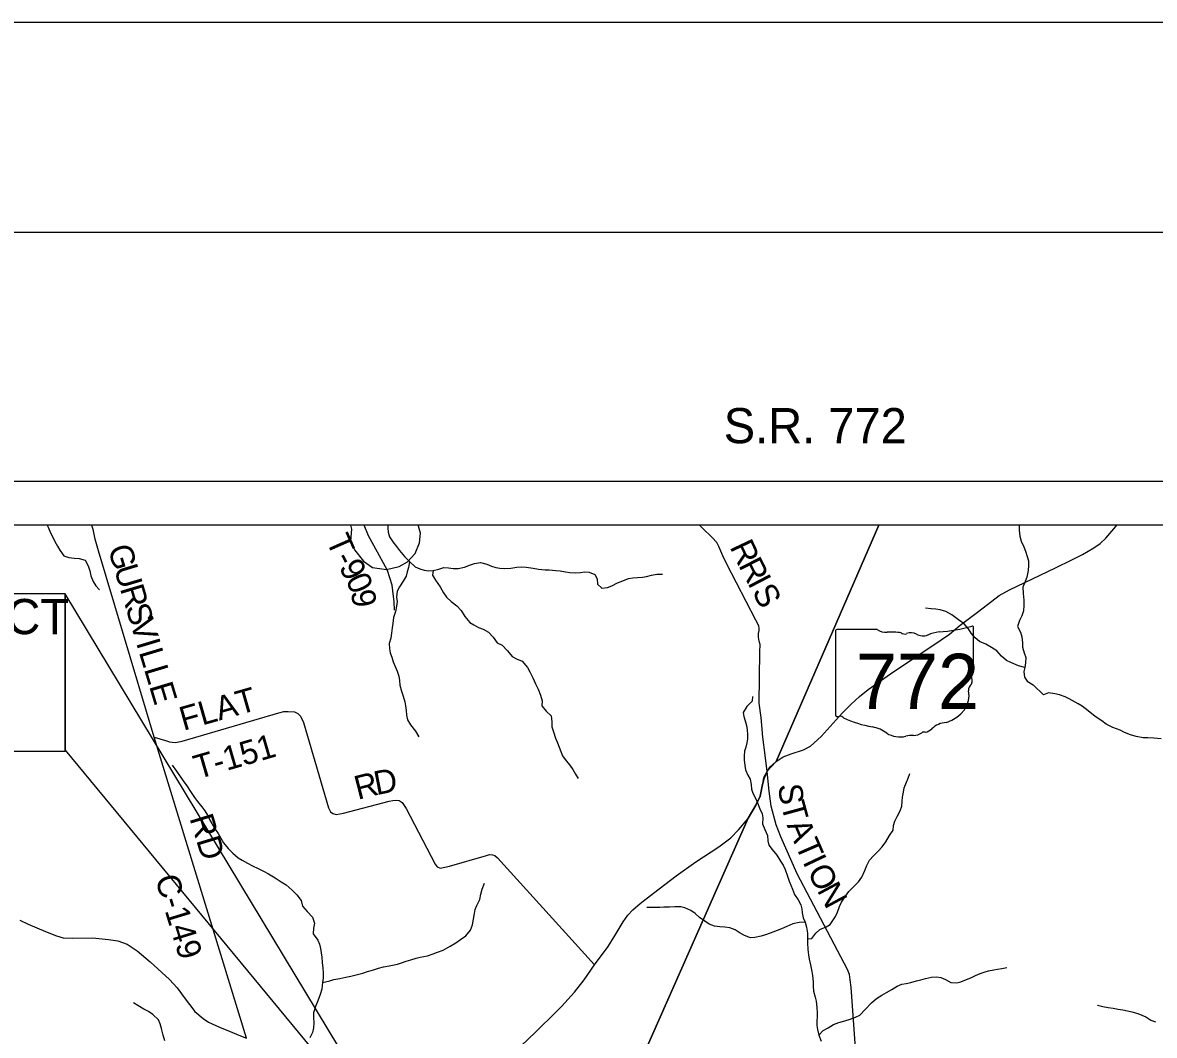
# Model space of a CAD drawing. Extents: x 0 to 34, y 0 to 22.
# Drawn here: x 3.817 to 6.52, y 19.582 to 22 of the extents above; entities that cross this region are included whole.
import ezdxf

# ---------------------------------------------------------------- set-up
doc = ezdxf.new("R2010")
doc.units = 0
for name, color, linetype in [('Default', 7, 'Continuous'), ('GM_X_County_Road', 7, 'Continuous'), ('GM_X_County_Road_Text', 7, 'Continuous'), ('GM_X_Minor_River', 7, 'Continuous'), ('GM_X_Rail_Line', 7, 'Continuous'), ('GM_X_State_Location', 7, 'Continuous'), ('GM_X_State_Route', 7, 'Continuous'), ('GM_X_State_Shield', 7, 'Continuous'), ('GM_X_Township_Road', 7, 'Continuous'), ('GM_X_Township_Road_Text', 7, 'Continuous'), ('SH_Border', 7, 'Continuous'), ('SH_Cut_Line', 7, 'Continuous'), ('SH_Text', 7, 'Continuous')]:
    doc.layers.add(name, color=color, linetype=linetype)

msp = doc.modelspace()

# ---------------------------------------------------------------- linework, layer by layer
at = {"layer": 'Default'}
for points in [[(9.087, 13.8822), (2.1062, 13.8822), (2.1062, 20.9054), (9.087, 20.9054)], [(5.8621, 20.8), (2.8183, 20.8), (3.0244, 19.9995), (3.1893, 19.3592), (4.7641, 19.2419), (4.831, 19.2363), (5.1554, 19.2083), (5.1782, 19.2598), (5.5496, 20.1004), (5.5679, 20.1313), (5.5783, 20.1528), (5.5834, 20.1771), (5.5869, 20.1933), (5.5951, 20.2127), (5.6047, 20.2229), (5.6166, 20.2359)], [(9, 18.8941), (9, 20.8), (5.8621, 20.8), (5.6166, 20.2359), (5.6047, 20.2229), (5.5951, 20.2127), (5.5869, 20.1933), (5.5834, 20.1771), (5.5783, 20.1528), (5.5679, 20.1313), (5.5496, 20.1004), (5.1782, 19.2598), (5.1554, 19.2083), (5.3224, 19.1939), (5.8337, 19.1499), (6.226, 19.1161), (6.8442, 19.0679), (8.0305, 18.9725), (8.8762, 18.9027)]]:
    msp.add_lwpolyline(points, close=True, dxfattribs=at)
at = {"layer": 'GM_X_County_Road'}
for points in [[(4.3522, 19.5749), (4.1318, 20.2937), (4.0556, 20.5466), (3.9987, 20.7384), (3.9908, 20.7664), (3.9869, 20.7867), (3.9826, 20.8)], [(3.8106, 19.8567), (3.8307, 19.8474), (3.8722, 19.8295), (3.898, 19.8193), (3.9145, 19.8144), (3.9359, 19.8139), (3.9841, 19.8144), (4.0229, 19.8108), (4.0448, 19.8072), (4.067, 19.7996), (4.0907, 19.784), (4.1222, 19.7574), (4.1679, 19.715), (4.1864, 19.6956), (4.2033, 19.6726), (4.2288, 19.6388), (4.2486, 19.6219), (4.2614, 19.6133), (4.2873, 19.6013), (4.3128, 19.5911), (4.3334, 19.5824), (4.3522, 19.5749)]]:
    msp.add_lwpolyline(points, dxfattribs=at)
at = {"layer": 'GM_X_Minor_River'}
for points in [[(3.8759, 20.8), (3.8782, 20.7951), (3.8841, 20.7821), (3.8893, 20.7714), (3.8944, 20.7611)], [(4.6898, 20.8), (4.6893, 20.7927), (4.6899, 20.7832), (4.6932, 20.7725), (4.7014, 20.7603), (4.7103, 20.7492), (4.717, 20.7392), (4.7293, 20.7254), (4.7416, 20.7135), (4.7547, 20.7008), (4.766, 20.6962), (4.7766, 20.693), (4.7871, 20.6913), (4.7981, 20.692), (4.811, 20.6952), (4.8232, 20.6989), (4.8341, 20.698), (4.8451, 20.6967), (4.8572, 20.6966), (4.8723, 20.6998), (4.8871, 20.7057), (4.8966, 20.7086), (4.911, 20.7107), (4.9261, 20.7072)], [(6.1973, 20.7991), (6.1972, 20.7881), (6.1985, 20.774), (6.2018, 20.7615), (6.2084, 20.7485), (6.2117, 20.7378), (6.2157, 20.7249), (6.219, 20.7146), (6.2196, 20.704), (6.2187, 20.6918), (6.2155, 20.6759), (6.2112, 20.6657), (6.2054, 20.6522), (6.2064, 20.637), (6.2077, 20.6206), (6.2083, 20.6085), (6.207, 20.5956), (6.2035, 20.5835), (6.198, 20.5722), (6.193, 20.5582), (6.2, 20.5448), (6.2033, 20.5334), (6.205, 20.5194), (6.2052, 20.5091), (6.2089, 20.4954), (6.2125, 20.484), (6.2124, 20.4711), (6.2104, 20.4605), (6.2083, 20.4507), (6.2093, 20.4374), (6.216, 20.4274), (6.2303, 20.4189)], [(3.8944, 20.7611), (3.9007, 20.75), (3.9063, 20.7401), (3.916, 20.7271), (3.9277, 20.7228), (3.9409, 20.7215), (3.9526, 20.7202), (3.9669, 20.7162), (3.9743, 20.7029), (3.9776, 20.6907), (3.9801, 20.6793), (3.9856, 20.6656), (3.9923, 20.6556), (4.0009, 20.6453)], [(4.7416, 20.7135), (4.7388, 20.6987), (4.7357, 20.6885), (4.7333, 20.6783), (4.726, 20.6667), (4.7171, 20.6531), (4.7121, 20.6425), (4.7104, 20.6285), (4.7114, 20.6179), (4.7105, 20.6065), (4.7077, 20.594), (4.7034, 20.5793), (4.7013, 20.5653), (4.7001, 20.555), (4.6984, 20.5422), (4.6964, 20.5304), (4.6928, 20.5176), (4.6931, 20.505), (4.6948, 20.4955), (4.6993, 20.4849), (4.7025, 20.4738), (4.7121, 20.4517), (4.7154, 20.4395), (4.7171, 20.4289), (4.7185, 20.4182), (4.7218, 20.4038), (4.7262, 20.392), (4.7298, 20.3783), (4.7316, 20.3688), (4.7329, 20.3574), (4.7339, 20.3463), (4.7365, 20.3353), (4.7439, 20.3231), (4.7558, 20.3078), (4.7636, 20.2944)], [(4.9261, 20.7072), (4.937, 20.7025), (4.9472, 20.6986), (4.957, 20.6973), (4.9691, 20.6968), (4.9831, 20.6974), (4.9971, 20.6995), (5.0096, 20.7005), (5.0198, 20.7), (5.0364, 20.6971), (5.0496, 20.6951), (5.0651, 20.6934), (5.0749, 20.6932), (5.0904, 20.6915), (5.1006, 20.691), (5.1134, 20.689), (5.1244, 20.6873), (5.1369, 20.6864), (5.1497, 20.6874), (5.1596, 20.6884), (5.1701, 20.6879), (5.1841, 20.6825), (5.1892, 20.6718), (5.1898, 20.6589), (5.2003, 20.6496), (5.214, 20.651), (5.2246, 20.6554), (5.2375, 20.6621), (5.2504, 20.6673), (5.2645, 20.6728), (5.2743, 20.6746), (5.2853, 20.6748), (5.2978, 20.6758), (5.3073, 20.6776), (5.3187, 20.6809), (5.3316, 20.6834), (5.3455, 20.6832)], [(4.7981, 20.692), (4.7965, 20.6806), (4.8035, 20.6684), (4.8143, 20.6527), (4.8224, 20.6386), (4.8295, 20.6279), (4.8404, 20.6182), (4.8542, 20.6075), (4.8647, 20.596), (4.8736, 20.5822), (4.8851, 20.5676), (4.8949, 20.5618), (4.9062, 20.556), (4.9171, 20.5517), (4.9302, 20.5443), (4.9407, 20.5325), (4.9504, 20.5194), (4.9628, 20.5132), (4.9755, 20.4998), (4.9867, 20.4864), (4.9964, 20.481), (5.01, 20.4751), (5.023, 20.4602), (5.0282, 20.4498), (5.036, 20.4353), (5.0419, 20.4212), (5.0485, 20.4083), (5.054, 20.3942), (5.0576, 20.3804), (5.0575, 20.3683), (5.0679, 20.356), (5.0795, 20.3449), (5.0809, 20.3301), (5.0811, 20.3187), (5.0848, 20.3069), (5.0902, 20.2913), (5.0943, 20.2806), (5.0987, 20.2699), (5.1027, 20.2593), (5.1068, 20.249), (5.1153, 20.2371), (5.1239, 20.2272), (5.1313, 20.2164), (5.1373, 20.2054), (5.1436, 20.1954)], [(6.2104, 20.4605), (6.1953, 20.4641), (6.1768, 20.4723), (6.1663, 20.4773), (6.1547, 20.4873), (6.1439, 20.5004), (6.1311, 20.5081), (6.1176, 20.5158), (6.1022, 20.5221), (6.0917, 20.5313), (6.0827, 20.5424), (6.0757, 20.5524), (6.0656, 20.5643), (6.0517, 20.5739), (6.0364, 20.5862), (6.0217, 20.5936), (6.0082, 20.598), (5.9976, 20.5996), (5.987, 20.6005), (5.973, 20.6022)], [(6.5359, 20.2898), (6.5185, 20.2911), (6.5044, 20.292), (6.4934, 20.2925), (6.4764, 20.2957), (6.4624, 20.2997), (6.4484, 20.3051), (6.4379, 20.3105), (6.4205, 20.3172), (6.405, 20.3253), (6.3941, 20.3326), (6.3787, 20.3434), (6.3618, 20.3568), (6.3475, 20.3676), (6.3377, 20.3734), (6.3166, 20.3854), (6.3067, 20.39), (6.2931, 20.3947), (6.2818, 20.3975), (6.267, 20.3995), (6.2552, 20.3951), (6.2303, 20.4189)], [(5.5603, 20.3908), (5.5594, 20.3802), (5.5464, 20.3674), (5.5383, 20.3524), (5.5393, 20.3429), (5.5426, 20.3326), (5.5455, 20.3216), (5.5473, 20.3113), (5.5486, 20.3006), (5.5485, 20.29), (5.5469, 20.2802), (5.5445, 20.2703), (5.5414, 20.2601), (5.5405, 20.2495), (5.5404, 20.2397), (5.5417, 20.2264), (5.5435, 20.2157), (5.5494, 20.2035), (5.5546, 20.1932), (5.5567, 20.1807), (5.5581, 20.1697), (5.561, 20.1601), (5.568, 20.1468), (5.5724, 20.1372), (5.5779, 20.1231), (5.5831, 20.1106), (5.5849, 20.101), (5.5839, 20.087), (5.5895, 20.0737), (5.5961, 20.0592), (5.5967, 20.0463), (5.5996, 20.0356), (5.6074, 20.026), (5.6186, 20.0119), (5.6271, 19.9977), (5.6331, 19.9882), (5.6379, 19.9775), (5.6437, 19.9623), (5.6481, 19.9497), (5.6559, 19.931), (5.6602, 19.9181), (5.6692, 19.9051), (5.6758, 19.8932), (5.6784, 19.8837), (5.679, 19.8742), (5.6815, 19.8628), (5.6859, 19.8518), (5.6888, 19.8403), (5.6913, 19.8255), (5.6915, 19.8122), (5.6918, 19.8024), (5.6927, 19.7872), (5.6941, 19.7739), (5.6955, 19.764), (5.6987, 19.7503), (5.7016, 19.7347), (5.7034, 19.7245), (5.7047, 19.71), (5.705, 19.6994), (5.7059, 19.6876), (5.7099, 19.6728), (5.7121, 19.6633), (5.7142, 19.6481), (5.7148, 19.636), (5.7147, 19.6265), (5.7138, 19.6159), (5.7137, 19.6056), (5.7151, 19.5957), (5.7183, 19.5821), (5.7238, 19.5683)], [(4.1748, 20.227), (4.1845, 20.2129), (4.1938, 20.1999), (4.2005, 20.1895), (4.2094, 20.1777), (4.2183, 20.1643), (4.2276, 20.1501), (4.235, 20.1406), (4.2455, 20.1275), (4.2525, 20.1176), (4.2589, 20.108), (4.2637, 20.0974), (4.2692, 20.0874), (4.2759, 20.0767), (4.2841, 20.0641), (4.2904, 20.053), (4.297, 20.0416), (4.3082, 20.0282), (4.3191, 20.0167), (4.3318, 20.0059), (4.3415, 20.0001), (4.3547, 19.9931), (4.3667, 19.9869), (4.3799, 19.9803), (4.3923, 19.9737), (4.4047, 19.9675), (4.4205, 19.9578), (4.4347, 19.9485), (4.4464, 19.9412), (4.4609, 19.9285), (4.4725, 19.917), (4.4822, 19.904), (4.4855, 19.8906), (4.497, 19.8772), (4.5097, 19.8638), (4.5145, 19.8501), (4.5117, 19.8376), (4.5112, 19.8243), (4.5223, 19.809), (4.526, 19.7995), (4.5289, 19.7892), (4.5317, 19.7687), (4.533, 19.7562), (4.5344, 19.7425), (4.5354, 19.7311), (4.5349, 19.7186), (4.5336, 19.708), (4.5315, 19.6921), (4.5276, 19.6796), (4.5221, 19.6641), (4.5171, 19.6505), (4.5123, 19.6354), (4.5122, 19.6252), (4.5124, 19.6107), (4.5119, 19.5998), (4.5095, 19.5884), (4.503, 19.576)], [(5.6915, 19.8122), (5.7017, 19.8133), (5.7113, 19.826), (5.7209, 19.8347), (5.7365, 19.8409), (5.746, 19.8465), (5.7587, 19.8653), (5.763, 19.8763), (5.7677, 19.8899), (5.7727, 19.9), (5.7804, 19.9121), (5.7904, 19.9252), (5.8, 19.9346), (5.813, 19.9481), (5.8211, 19.9594), (5.8288, 19.9752), (5.8335, 19.9873), (5.8393, 20.0002), (5.8489, 20.0103), (5.8604, 20.0219), (5.8695, 20.0317), (5.8788, 20.0437), (5.8876, 20.0588), (5.8961, 20.0719), (5.897, 20.0826), (5.8998, 20.0931), (5.9059, 20.1045), (5.9129, 20.1176), (5.9164, 20.129), (5.9177, 20.1407), (5.9186, 20.1506), (5.9206, 20.1627), (5.9226, 20.1729), (5.9277, 20.1861), (5.932, 20.1963), (5.9355, 20.2073)], [(4.5336, 19.708), (4.5511, 19.7123), (4.5609, 19.7152), (4.5749, 19.7174), (4.5894, 19.721), (4.6011, 19.7231), (4.614, 19.7264), (4.6295, 19.7304), (4.6409, 19.734), (4.6531, 19.7377), (4.6671, 19.7421), (4.6793, 19.7457), (4.6925, 19.7478), (4.7122, 19.7521), (4.7225, 19.7551), (4.7335, 19.7587), (4.7445, 19.7624), (4.7574, 19.7664), (4.7669, 19.7682), (4.7839, 19.7718), (4.798, 19.7762), (4.8082, 19.7802), (4.8215, 19.7854), (4.8383, 19.795), (4.8516, 19.8028), (4.8627, 19.8111), (4.8756, 19.8193), (4.8867, 19.8328), (4.8918, 19.8456), (4.8942, 19.8592), (4.8963, 19.8725), (4.8983, 19.8823), (4.9022, 19.8921), (4.9091, 19.9065), (4.9119, 19.9186), (4.9144, 19.9311), (4.9206, 19.9454)], [(5.6859, 19.8518), (5.6716, 19.8515), (5.6564, 19.8483), (5.642, 19.842), (5.6294, 19.8365), (5.6089, 19.8284), (5.5933, 19.8225), (5.5808, 19.8185), (5.566, 19.8152), (5.5551, 19.815), (5.5415, 19.8205), (5.531, 19.8259), (5.5186, 19.834), (5.5058, 19.8383), (5.4941, 19.8404), (5.482, 19.8413), (5.4692, 19.8429), (5.4571, 19.8473), (5.4462, 19.8542), (5.4339, 19.8635), (5.423, 19.8727), (5.4129, 19.88), (5.399, 19.8866), (5.3888, 19.8887), (5.3744, 19.8888), (5.3619, 19.8882), (5.3487, 19.8876), (5.3389, 19.8874), (5.3241, 19.8875), (5.3078, 19.887)], [(5.7183, 19.5821), (5.729, 19.5937), (5.7408, 19.6), (5.7538, 19.6078), (5.7667, 19.6126), (5.7807, 19.6162), (5.7936, 19.6206), (5.8062, 19.625), (5.8161, 19.6298), (5.8295, 19.6437), (5.8444, 19.6595), (5.8566, 19.6696), (5.8688, 19.6781), (5.8802, 19.6841), (5.8932, 19.6915), (5.9057, 19.6997), (5.9171, 19.7041), (5.927, 19.7059), (5.9384, 19.7077), (5.952, 19.7117), (5.9619, 19.7142), (5.9736, 19.7179), (5.9877, 19.7207), (5.9998, 19.7213), (6.0096, 19.7197), (6.0212, 19.715), (6.0336, 19.708), (6.048, 19.7075), (6.0579, 19.71), (6.0674, 19.7133), (6.0818, 19.7196), (6.0924, 19.7244), (6.1039, 19.7296), (6.1133, 19.7329), (6.124, 19.7358), (6.1361, 19.7383), (6.1456, 19.7401), (6.1554, 19.7415), (6.1672, 19.7436)], [(4.1573, 19.5691), (4.1533, 19.5824), (4.1493, 19.598), (4.1456, 19.609), (4.1416, 19.6189), (4.1285, 19.6316), (4.118, 19.6386), (4.1067, 19.6444), (4.0928, 19.6529), (4.0819, 19.6595)], [(6.384, 19.6536), (6.3965, 19.6508), (6.4094, 19.6484), (6.4211, 19.6464), (6.4332, 19.6447), (6.4446, 19.6431), (6.456, 19.6407), (6.4658, 19.6383), (6.4802, 19.634), (6.499, 19.6262), (6.5115, 19.6185), (6.5228, 19.6142)]]:
    msp.add_lwpolyline(points, dxfattribs=at)
at = {"layer": 'GM_X_Rail_Line'}
msp.add_lwpolyline([(4.6, 20.8), (4.6025, 20.7907), (4.6, 20.7626), (4.6097, 20.7414), (4.631, 20.7138), (4.6529, 20.6992), (4.6859, 20.6946), (4.7167, 20.7017), (4.7364, 20.7124), (4.7545, 20.7322), (4.7647, 20.7578), (4.7676, 20.7806), (4.763, 20.7976), (4.7621, 20.8)], dxfattribs=at)
at = {"layer": 'GM_X_State_Route'}
for points in [[(5.5953, 20.2121), (5.6027, 20.2231), (5.6168, 20.2354), (5.6332, 20.2466), (5.6525, 20.2544), (5.6816, 20.2634), (5.6988, 20.2723), (5.7245, 20.2952), (5.774, 20.3512), (5.7951, 20.372), (5.8153, 20.3907), (5.8361, 20.4078), (5.8895, 20.4454), (6.0108, 20.5264), (6.0305, 20.5396), (6.0563, 20.5611), (6.1008, 20.5948), (6.1494, 20.632), (6.1739, 20.6453), (6.2833, 20.6982), (6.323, 20.7174), (6.348, 20.7304), (6.3749, 20.7463), (6.3907, 20.7566), (6.4041, 20.7692), (6.4277, 20.7971), (6.4304, 20.8)], [(5.0927, 19.6394), (5.1042, 19.6509), (5.1355, 19.6853), (5.1579, 19.7145), (5.1829, 19.7506), (5.2155, 19.794), (5.2321, 19.8208), (5.251, 19.8532), (5.2628, 19.869), (5.2747, 19.8819), (5.2923, 19.8966), (5.3241, 19.9213), (5.3778, 19.9629), (5.4246, 19.9963), (5.4799, 20.0317), (5.5083, 20.0537), (5.5264, 20.0722), (5.5498, 20.0999), (5.5682, 20.1307), (5.5785, 20.1523), (5.5837, 20.1766), (5.5872, 20.1973), (5.5953, 20.2121)], [(4.7822, 19.2658), (4.8193, 19.3162), (4.8615, 19.3727), (4.9164, 19.4541), (4.9387, 19.4846), (4.9923, 19.5416), (5.0416, 19.5883), (5.0927, 19.6394)]]:
    msp.add_lwpolyline(points, dxfattribs=at)
at = {"layer": 'GM_X_State_Shield'}
for p, q in [((5.7581, 20.5471), (5.7581, 20.347)), ((5.8579, 20.5506), (5.7614, 20.5506)), ((6.0877, 20.4508), (6.0877, 20.5555)), ((6.0877, 20.4509), (6.0877, 20.4508))]:
    msp.add_line(p, q, dxfattribs=at)
for centre, major_axis, start_param, end_param in [((5.7619, 20.5476), (0.00382, 0), 1.712693, 3.28349), ((5.8809, 20.5738), (0.037, 0), 4.042523, 4.731795), ((5.8932, 20.4382), (0.133, 0), 1.404758, 1.657858), ((5.9234, 20.5486), (0.0107, 0), 3.836095, 5.185415), ((5.939, 20.5255), (0.0222, 0), 0.950623, 2.079405), ((5.9677, 20.5572), (0.0267, 0), 4.081561, 5.145723), ((6.0149, 20.4894), (0.0703, 0), 1.699011, 2.107814), ((5.9703, 20.8234), (0.3495, 0), 4.814394, 5.042369), ((6.0841, 20.556), (0.00367, 0), 6.141152, 7.989035), ((6.0869, 20.4432), (0.00568, 0), 1.883978, 3.671073), ((6.0508, 20.4299), (0.0341, 0), 5.934695, 6.695948), ((6.0838, 20.4504), (0.00393, 0), 5.05454, 6.418171), ((5.9899, 20.3937), (0.0874, 0), 5.101752, 6.440018), ((6.1009, 20.407), (0.0248, 0), 2.387724, 3.262537), ((5.762, 20.3466), (0.00385, 0), 3.00124, 4.508301), ((5.7625, 20.367), (0.0294, 0), 4.665946, 4.897461), ((5.7686, 20.3355), (0.0106, 0), 0.519207, 1.627899), ((5.9024, 20.5153), (0.2524, 0), 4.195997, 4.488961), ((6.0268, 20.2908), (0.0479, 0), 1.647645, 2.488434), ((5.8271, 20.2571), (0.079, 0), 0.823519, 1.323587), ((5.9125, 20.3345), (0.0501, 0), 4.026481, 4.996735), ((5.9415, 20.2653), (0.0412, 0), 1.495662, 1.94098), ((5.9452, 20.3195), (0.0267, 0), 4.691044, 5.507374), ((5.9693, 20.3001), (0.00752, 0), 1.147584, 2.315152), ((5.9661, 20.3276), (0.0282, 0), 4.937069, 5.64225)]:
    msp.add_ellipse(centre, major_axis=major_axis, ratio=0.8, start_param=start_param, end_param=end_param, dxfattribs=at)
at = {"layer": 'GM_X_Township_Road'}
for points in [[(4.7056, 20.5969), (4.7044, 20.6167), (4.7014, 20.6434), (4.7, 20.6571), (4.6885, 20.6917), (4.6649, 20.7354), (4.6434, 20.7748), (4.6326, 20.8)], [(5.5904, 20.2509), (5.585, 20.2935), (5.5811, 20.3409), (5.5758, 20.3752), (5.5777, 20.498), (5.5786, 20.515), (5.5758, 20.5231), (5.5753, 20.5276), (5.5746, 20.533), (5.5749, 20.541), (5.5759, 20.5482), (5.576, 20.5535), (5.5751, 20.5596), (5.5683, 20.5732), (5.499, 20.7069), (5.489, 20.7266), (5.4795, 20.7493), (5.4748, 20.7589), (5.4642, 20.7707), (5.441, 20.7931), (5.4337, 20.8)], [(4.1318, 20.2937), (4.1588, 20.286), (4.1682, 20.2826), (4.1746, 20.2817), (4.1822, 20.2814), (4.1982, 20.2844), (4.4292, 20.3516), (4.4415, 20.355), (4.4517, 20.3555), (4.4668, 20.3542), (4.4743, 20.3502), (4.4813, 20.3443), (4.4884, 20.3292), (4.5476, 20.1251), (4.5526, 20.1159), (4.5582, 20.1119), (4.5664, 20.1093), (4.5839, 20.1122), (4.6929, 20.1407), (4.7016, 20.1427), (4.7096, 20.1436), (4.7164, 20.1426), (4.7235, 20.1382), (4.7332, 20.1235), (4.8022, 19.9909), (4.807, 19.9843), (4.8148, 19.9807), (4.8366, 19.9861), (4.9253, 20.0114), (4.9322, 20.0135), (4.939, 20.0129), (4.945, 20.0111), (4.9513, 20.006), (5.1829, 19.7506)], [(5.8339, 19.1494), (5.8361, 19.1664), (5.8376, 19.1875), (5.8379, 19.2071), (5.8362, 19.2256), (5.8324, 19.2487), (5.8274, 19.2989), (5.8212, 19.3409), (5.8062, 19.5516), (5.7955, 19.6967), (5.7938, 19.7146), (5.7919, 19.7268), (5.7874, 19.7395), (5.6668, 19.9679), (5.628, 20.0558), (5.6168, 20.0847), (5.6048, 20.1295), (5.6, 20.1652), (5.5953, 20.2121), (5.5904, 20.2509)]]:
    msp.add_lwpolyline(points, dxfattribs=at)
at = {"layer": 'SH_Border'}
msp.add_lwpolyline([(1.5, 21.5), (33.5, 21.5), (33.5, 0.5), (1.5, 0.5)], close=True, dxfattribs=at)
at = {"layer": 'SH_Cut_Line'}
for points in [[(0, 0), (34, 0), (34, 22), (0, 22)], [(9, 18.8941), (9, 20.8), (2.2, 20.8), (2.2, 19.4329), (2.7961, 19.3885), (3.1893, 19.3592), (4.7641, 19.2419), (4.831, 19.2363), (5.1554, 19.2083), (5.3224, 19.1939), (5.8337, 19.1499), (6.226, 19.1161), (6.8442, 19.0679), (8.0305, 18.9725), (8.8762, 18.9027)]]:
    msp.add_lwpolyline(points, close=True, dxfattribs=at)
at = {"layer": 'SH_Text'}
for points in [[(3.9194, 20.6364), (3.1311, 20.6364), (3.1311, 20.2602), (3.9194, 20.2602)], [(4.7557, 19.2507), (3.9194, 20.6364), (3.9194, 20.2631)]]:
    msp.add_lwpolyline(points, close=True, dxfattribs=at)

# ---------------------------------------------------------------- texts
at = {"layer": 'Default'}
msp.add_text('   S.R. 772', height=0.084, dxfattribs=at).set_placement((5.3979, 20.9957))
at = {"layer": 'GM_X_County_Road_Text'}
for s, height, rotation, p in [('G', 0.0568, 286.7558, (4.0205, 20.7447)), ('U', 0.0568, 286.6895, (4.0349, 20.6969)), ('R', 0.0568, 286.6907, (4.0493, 20.649)), ('S', 0.0568, 286.6895, (4.0627, 20.6043)), ('V', 0.0568, 286.6905, (4.0737, 20.5676)), ('I', 0.0568, 286.6915, (4.088, 20.5197)), ('L', 0.0568, 286.6919, (4.0947, 20.4973)), ('L', 0.0568, 286.6871, (4.1069, 20.4566)), ('E', 0.0568, 286.6894, (4.1191, 20.4159)), ('RD', 0.05682, 287.0303, (4.2154, 20.1004)), ('C-149', 0.05682, 287.0423, (4.133, 19.9566))]:
    msp.add_text(s, height=height, rotation=rotation, dxfattribs=at).set_placement(p)
at = {"layer": 'GM_X_State_Location'}
for s in ['s', 'r']:
    msp.add_text(s, height=0.000189, dxfattribs=at).set_placement((5.9192, 20.4338))
msp.add_text('772', height=0.000189, rotation=0, dxfattribs=at).set_placement((5.8524, 20.42))
at = {"layer": 'GM_X_State_Shield'}
msp.add_text('772', height=0.13184, dxfattribs=at).set_placement((5.8071, 20.3611))
at = {"layer": 'GM_X_Township_Road_Text'}
for s, height, rotation, p in [('T', 0.0568, 293.8511, (4.5412, 20.7638)), ('R', 0.0568, 295.3231, (5.505, 20.7484)), ('-', 0.0568, 298.0155, (4.5603, 20.7209)), ('9', 0.0568, 298.3765, (4.5715, 20.7)), ('R', 0.0568, 297.2732, (5.5259, 20.7043)), ('0', 0.0568, 294.3012, (4.5877, 20.6701)), ('I', 0.0568, 297.4384, (5.5474, 20.6627)), ('9', 0.0568, 279.0773, (4.6009, 20.642)), ('S', 0.0568, 297.4363, (5.5581, 20.642)), ('FLAT', 0.05682, 15.9076, (4.2015, 20.3088)), ('T-151', 0.05682, 16.2151, (4.2358, 20.1933)), ('D', 0.0568, 11.0531, (4.6622, 20.1553)), ('R', 0.0568, 14.2757, (4.6178, 20.144)), ('S', 0.0568, 276.5139, (5.6214, 20.1802)), ('T', 0.0568, 285.2295, (5.6276, 20.1328)), ('A', 0.0568, 292.872, (5.6414, 20.084)), ('T', 0.0568, 293.508, (5.6611, 20.0373)), ('I', 0.0568, 295.3598, (5.6789, 19.9965)), ('O', 0.0568, 297.2497, (5.6898, 19.9736)), ('N', 0.0568, 298.142, (5.7132, 19.9283))]:
    msp.add_text(s, height=height, rotation=rotation, dxfattribs=at).set_placement(p)
at = {"layer": 'SH_Text'}
msp.add_text('END PROJECT', height=0.084, dxfattribs=at).set_placement((3.1358, 20.5398))

doc.saveas('drawing.dxf')
